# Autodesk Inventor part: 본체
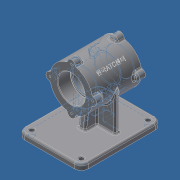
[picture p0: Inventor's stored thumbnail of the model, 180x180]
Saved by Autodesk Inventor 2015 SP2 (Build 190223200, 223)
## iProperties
Created: 2015-12
Part Number: 본체
Material: 일반
Document SubType Name: Modeling
Designer: AMC
Density: 1 g/cm^3
Appearance: 기본값
Author: AMC
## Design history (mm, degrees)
sketch "스케치1"
  geometry: L1 (-55, -70)-(55, -70); L2 (55, -70)-(55, -80); L3 (55, -80)-(-55, -80); L4 (-55, -80)-(-55, -70); C1 r 37 at (0, 0); 2 further points
  constraints: 8 end point, 2 parallel, 1 centre point, 1 coincident, 1 horizontal, 1 midpoint, 1 perpendicular, 1 vertical alignment
  dimensions: "d0" = 74 diameter of C1; "d1" = 110 distance of L1.start L1.end; "d2" = 10 distance of L3.end L1.start; "d3" = 80 distance from line of L3 point (0, 0)
extrude "돌출1" new body sketch "스케치1" stored distance "d4" = 85; taper "d5" = 0 deg
extrude "돌출2" join sketch "스케치1" distance "d6" = 80; taper "d8" = 0 deg; dims "d7" = 60, "d9" = 0
node "작업 평면1"
sketch "스케치2"
  geometry: L1 (55, -70)-(-55, -70) reference; L2 (37, 0)-(37, -70); L3 (-37, 0)-(-37, -70); L4 (-37, -70)-(37, -70); A1 r 37 centre (0, 0) between (37, 0) and (-37, 0) reference; A2 r 37 centre (0, 0) between (-37, 0) and (37, 0); 1 further point
  constraints: 6 end point, 4 point on circle, 2 perpendicular, 2 point on line, 2 tangent, 1 centre point, 1 coincident, 1 horizontal
extrude "돌출3" join sketch "스케치2" stored distance "d11" = 8; taper "d12" = 0 deg
node "작업 평면2"
sketch "스케치3"
  geometry: L1 (-70, 80)-(-70, -60) reference; L2 (-70, 4)-(0, 4) reference; L3 (-37, -42.5)-(-37, 42.5) reference; L4 (-37, 20.948)-(-70, 25); L5 (0, 0)-(-70, 0)
  constraints: 4 end point, 3 point on line, 1 perpendicular
  dimensions: "d14" = 25 distance of L4.end L5.end; "d15" = 97 deg angle of L1 L4
feature "리브1" sketch "스케치3" dims "d16" = 1, "d17" = 12, "d18" = 0, "d19" = 0, "d20" = 1, "d21" = 1
fillet "모깎기1" dims "d22" = 12
sketch "스케치4"
  geometry: L1 (-12, 128)-(-12, 12) reference; L2 (86, 0)-(0, 0) reference; L3 (98, 12)-(98, 128) reference; L4 (0, 140)-(86, 140) reference; L5 (37, 55)-(37, 76) reference; L6 (37, 76)-(6, 76) reference; L7 (6, 76)-(6, 84) reference; L8 (6, 84)-(37, 84) reference; L9 (37, 84)-(37, 105) reference; L10 (37, 105)-(49, 105) reference; L11 (49, 105)-(49, 84) reference; L12 (49, 84)-(80, 84) reference; L13 (80, 84)-(80, 76) reference; L14 (80, 76)-(49, 76) reference; L15 (49, 76)-(49, 55) reference; L16 (49, 55)-(37, 55) reference; A1 r 12 centre (0, 12) between (-12, 12) and (0, 0) reference; A2 r 12 centre (0, 128) between (0, 140) and (-12, 128) reference; A3 r 12 centre (0, 12) between (-12, 12) and (0, 0) reference; A4 r 12 centre (86, 12) between (86, 0) and (98, 12) reference; A5 r 12 centre (86, 128) between (98, 128) and (86, 140) reference; 5 further points
  constraints: 4 coincident
hole "구멍1" sketch "스케치4" at (0, 12), (86, 12), (0, 128), (86, 128) diameter "d23" = 8; stored, may be unused: countersink angle "d27" = 90 deg, drill point angle "d29" = 118 deg; dims "d24" = 6, "d25" = 4, "d26" = 2, "d28" = 10
hole "구멍2" diameter "d32" = 42; stored, may be unused: countersink angle "d36" = 90 deg, drill point angle "d38" = 118 deg; dims "d30" = 10, "d31" = 10, "d33" = 6, "d34" = 47, "d35" = 22, "d37" = 10
hole "구멍3" diameter "d41" = 42; stored, may be unused: countersink angle "d45" = 90 deg, drill point angle "d47" = 118 deg; dims "d39" = 10, "d40" = 10, "d42" = 6, "d43" = 47, "d44" = 22, "d46" = 10
fillet "모깎기2" dims "d53" = 3
fillet "모깎기3" dims "d54" = 3
fillet "모깎기4" dims "d55" = 3
chamfer "모따기1" distance "d56" = 1; stored, may be unused: second distance "d57" = 2, angle "d58" = 45 deg
node "작업 평면3"
sketch "스케치6"
  geometry: L1 (0, 0)-(26.163, 26.163); L2 (0, 0)-(37, 0); 1 further point
  constraints: 4 end point, 1 equal length, 1 horizontal, 2 other
  dimensions: "d60" = 45 deg angle of L2 L1
node "작업 평면4"
sketch "스케치7"
  geometry: 2 further points
  constraints: 1 coincident, 1 other
feature "엠보싱1" sketch "스케치7" dims "d61" = 0.5, "d62" = 0
node "작업 평면6"
sketch "스케치11"
  geometry: L1 (0, 0)-(0, 37); A1 r 37 centre (0, 0) between (6.969, 36.338) and (-6.969, 36.338); A2 r 7 centre (0, 37) between (6.969, 36.338) and (-6.969, 36.338); 2 further points
  constraints: 4 point on circle, 3 coincident, 2 centre point, 2 end point, 1 vertical, 1 vertical alignment, 2 other
  dimensions: "d68" = 14 diameter of A2
extrude "돌출4" join sketch "스케치11" distance "d69" = 12.452; taper "d70" = 0 deg
node "작업 평면7"
sketch "스케치12"
  geometry: L1 (44, 42.5)-(44, 30.048) reference; L2 (36.338, 30.048)-(44, 30.048) reference; L3 (37, -42.5)-(37, 30.048) reference; L4 (44, 30.048)-(37, 27.5); L5 (44, 30.048)-(37, 30.048); L6 (37, 27.5)-(37, 30.048); L7 (37, 27.5)-(37, 30.048); 1 further point
  constraints: 8 end point, 3 collinear, 1 point on line
  dimensions: "d75" = 110 deg angle of L3 L4
revolve "회전1" sketch "스케치12" stored, may be unused: angle "d76" = 90 deg
fillet "모깎기5" dims "d77" = 3
hole "구멍4" diameter "d80" = 3.242; stored, may be unused: countersink angle "d84" = 90 deg, drill point angle "d86" = 118 deg; dims "d78" = 10, "d79" = 10, "d81" = 9, "d82" = 2, "d83" = 22, "d85" = 11
fillet "모깎기6" dims "d90" = 0.3
node "솔리드1"
mirror "대칭1"
pattern_circular "원형 패턴1" dims "d88" = 360 deg
mirror "대칭2"
node "투영된 루프1"
other parameters: "d10" = 0, "d13" = 0, "d59" = 0, "d67" = 0, "d71" = 0
